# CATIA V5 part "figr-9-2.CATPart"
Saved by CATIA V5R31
Part number: Part1
Bounding box of the stored display mesh (mm): x -25 to 69.61, y -139.735 to 0, z 0 to 45
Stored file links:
  D:\PROJECTS\Project 2021\US EDITION\CATIA V5 6R 2021\Resources\Part Files\c09_catia_v5_6r2021_prt\c09_catia_v5_6r2021_prt\figr-9-2.CATPart
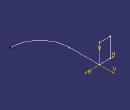
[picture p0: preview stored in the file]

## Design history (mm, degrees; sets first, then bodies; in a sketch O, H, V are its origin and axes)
Body1 (main body)
  Sketch1 on xy-plane, origin (0, 0, 0), H (1, 0, 0), V (0, 1, 0)
    line L1 (0, 0) -> (0, -70.1255)
    arc A1 centre (69.6095, -70.1255) radius 69.6095 from (0, -70.1255) to (69.6095, -139.7351) ccw
    vertical: L1 V
    tangency: A1 L1
  Sketch2 on zx-plane, origin (0, 0, 0), H (-1, 0, 0), V (0, 0, 1)
    point P1 (0, 0)
    line L1 (0, 0) -> (25, 0)
    line L2 (25, 0) -> (25, 45)
    line L3 (25, 45) -> (0, 45)
    line L4 (0, 45) -> (0, 0)
    length L3 = 25
    length L2 = 45
    coincidence: P1 H, P1 O
    horizontal: L1 H, L3 H
    vertical: L2 V, L4 V
  Rib1: profile Sketch2, centre curve Sketch1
